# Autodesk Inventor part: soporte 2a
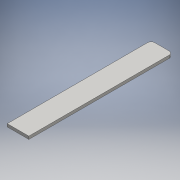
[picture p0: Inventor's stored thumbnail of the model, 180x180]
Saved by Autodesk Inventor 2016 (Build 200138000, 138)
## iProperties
Created: 2016-06
Part Number: soporte 2a
Material: Genérico
Document SubType Name: Modeling
Designer: adm
Density: 1 g/cm^3
Appearance: Valor por defecto
Author: adm
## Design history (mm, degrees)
sketch "Boceto1"
  geometry: L1 (-15, -100)-(15, -100); L2 (15, -100)-(15, 100); L3 (15, 100)-(-15, 100); L4 (-15, 100)-(-15, -100); L5 (-15, -100)-(15, 100); L6 (15, -100)-(-15, 100); 1 further point
  constraints: 12 end point, 2 midpoint, 2 parallel, 1 horizontal, 1 perpendicular
  dimensions: "d0" = 30 distance of L2.end L3.end; "d1" = 200 distance of L3.end L1.start
extrude "Extrusión1" new body sketch "Boceto1" distance "d2" = 4; taper "d3" = 0 deg
fillet "Empalme1" dims "d4" = 5
node "Sólido1"
